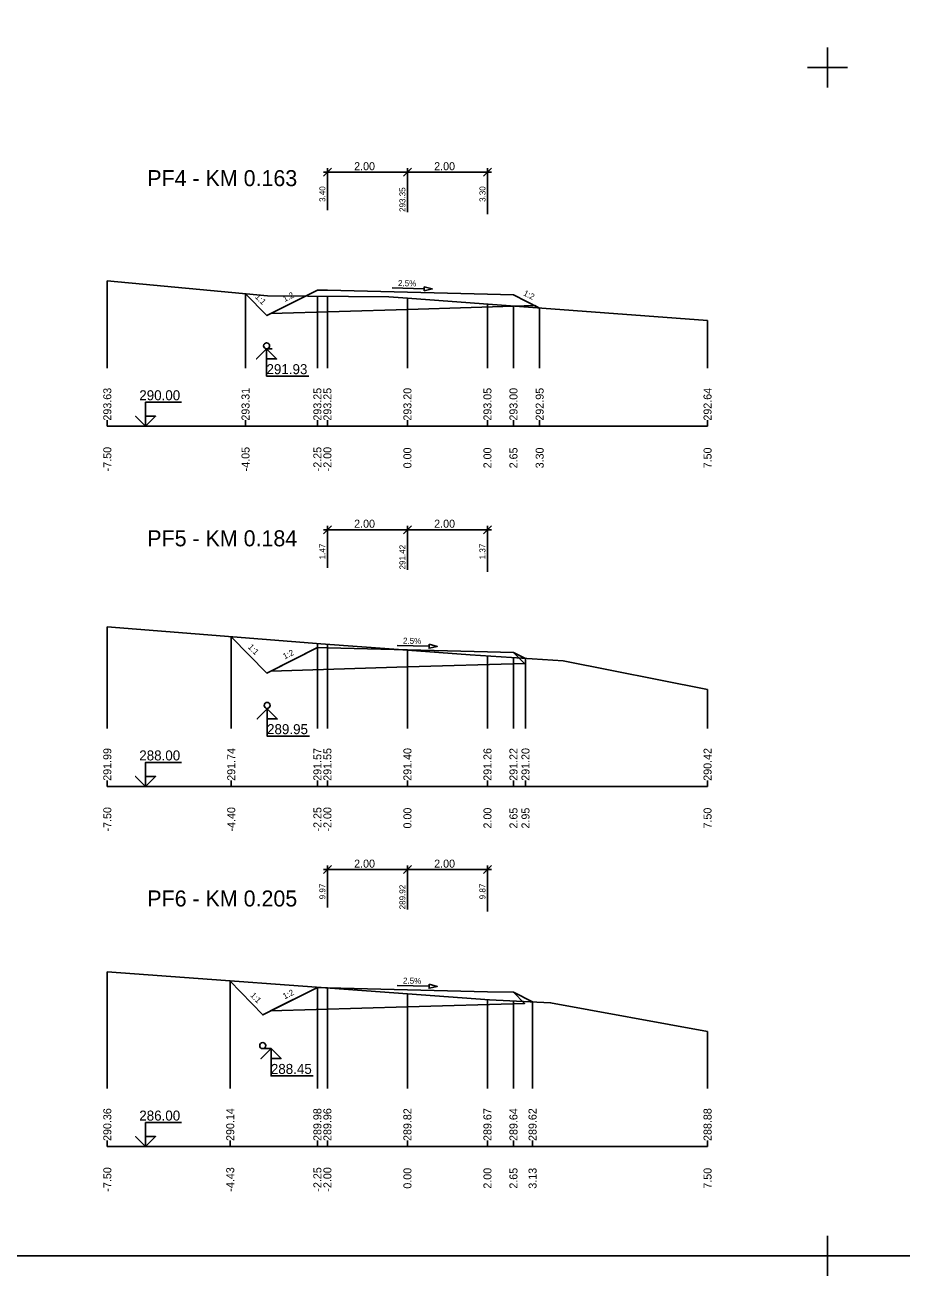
# Model space of a CAD drawing. Extents: x -5 to 1895, y -2 to 602.
# Drawn here: x 219.4 to 438.6, y -2.3 to 310.3 of the extents above; entities that cross this region are included whole.
import ezdxf

# ---------------------------------------------------------------- set-up
doc = ezdxf.new("R2010")
doc.units = 0
for name, color, linetype in [('KOTA', 7, 'Continuous'), ('KOTA_DELKY', 7, 'Continuous'), ('KOTA_DELKY_CONT', 7, 'Continuous'), ('KRIZENI', 7, 'Continuous'), ('NS_TELESO_VOZOVKY', 7, 'Continuous'), ('NS_V_PF', 7, 'Continuous'), ('REZY_PF_PUVODNI', 7, 'Continuous'), ('SESTAVY_REZU_PF', 7, 'Continuous'), ('SKLON', 7, 'Continuous'), ('SVK', 7, 'Continuous')]:
    doc.layers.add(name, color=color, linetype=linetype)

msp = doc.modelspace()

# ---------------------------------------------------------------- linework, layer by layer
for p, q in [((420, 304.67), (420, 294.67)), ((420, 304.67), (420, 294.67)), ((420, 304.67), (420, 294.67)), ((420, 304.67), (420, 294.67)), ((420, 304.67), (420, 294.67)), ((420, 304.67), (420, 294.67)), ((420, 304.67), (420, 294.67)), ((420, 304.67), (420, 294.67)), ((420, 304.67), (420, 294.67)), ((420, 304.67), (420, 294.67)), ((420, 304.67), (420, 294.67)), ((420, 304.67), (420, 294.67)), ((420, 304.67), (420, 294.67)), ((420, 304.67), (420, 294.67)), ((420, 304.67), (420, 294.67)), ((420, 304.67), (420, 294.67)), ((420, 304.67), (420, 294.67)), ((420, 304.67), (420, 294.67)), ((420, 304.67), (420, 294.67)), ((420, 304.67), (420, 294.67)), ((420, 304.67), (420, 294.67)), ((420, 304.67), (420, 294.67)), ((420, 304.67), (420, 294.67)), ((420, 304.67), (420, 294.67)), ((420, 304.67), (420, 294.67)), ((420, 304.67), (420, 294.67)), ((420, 304.67), (420, 294.67)), ((420, 304.67), (420, 294.67)), ((420, 304.67), (420, 294.67)), ((420, 304.67), (420, 294.67)), ((420, 304.67), (420, 294.67)), ((420, 304.67), (420, 294.67)), ((420, 304.67), (420, 294.67)), ((420, 304.67), (420, 294.67)), ((420, 304.67), (420, 294.67)), ((420, 304.67), (420, 294.67)), ((420, 304.67), (420, 294.67)), ((420, 304.67), (420, 294.67)), ((420, 304.67), (420, 294.67)), ((420, 304.67), (420, 294.67)), ((420, 304.67), (420, 294.67)), ((420, 304.67), (420, 294.67)), ((420, 304.67), (420, 294.67)), ((420, 304.67), (420, 294.67)), ((420, 304.67), (420, 294.67)), ((420, 304.67), (420, 294.67)), ((420, 304.67), (420, 294.67)), ((420, 304.67), (420, 294.67)), ((420, 304.67), (420, 294.67)), ((420, 304.67), (420, 294.67)), ((420, 304.67), (420, 294.67)), ((420, 304.67), (420, 294.67)), ((420, 304.67), (420, 294.67)), ((420, 304.67), (420, 294.67)), ((425, 299.67), (415, 299.67)), ((425, 299.67), (415, 299.67)), ((425, 299.67), (415, 299.67)), ((425, 299.67), (415, 299.67)), ((425, 299.67), (415, 299.67)), ((425, 299.67), (415, 299.67)), ((425, 299.67), (415, 299.67)), ((425, 299.67), (415, 299.67)), ((425, 299.67), (415, 299.67)), ((425, 299.67), (415, 299.67)), ((425, 299.67), (415, 299.67)), ((425, 299.67), (415, 299.67)), ((425, 299.67), (415, 299.67)), ((425, 299.67), (415, 299.67)), ((425, 299.67), (415, 299.67)), ((425, 299.67), (415, 299.67)), ((425, 299.67), (415, 299.67)), ((425, 299.67), (415, 299.67)), ((425, 299.67), (415, 299.67)), ((425, 299.67), (415, 299.67)), ((425, 299.67), (415, 299.67)), ((425, 299.67), (415, 299.67)), ((425, 299.67), (415, 299.67)), ((425, 299.67), (415, 299.67)), ((425, 299.67), (415, 299.67)), ((425, 299.67), (415, 299.67)), ((425, 299.67), (415, 299.67)), ((425, 299.67), (415, 299.67)), ((425, 299.67), (415, 299.67)), ((425, 299.67), (415, 299.67)), ((425, 299.67), (415, 299.67)), ((425, 299.67), (415, 299.67)), ((425, 299.67), (415, 299.67)), ((425, 299.67), (415, 299.67)), ((425, 299.67), (415, 299.67)), ((425, 299.67), (415, 299.67)), ((425, 299.67), (415, 299.67)), ((425, 299.67), (415, 299.67)), ((425, 299.67), (415, 299.67)), ((425, 299.67), (415, 299.67)), ((425, 299.67), (415, 299.67)), ((425, 299.67), (415, 299.67)), ((425, 299.67), (415, 299.67)), ((425, 299.67), (415, 299.67)), ((425, 299.67), (415, 299.67)), ((425, 299.67), (415, 299.67)), ((425, 299.67), (415, 299.67)), ((425, 299.67), (415, 299.67)), ((425, 299.67), (415, 299.67)), ((425, 299.67), (415, 299.67)), ((425, 299.67), (415, 299.67)), ((425, 299.67), (415, 299.67)), ((425, 299.67), (415, 299.67)), ((425, 299.67), (415, 299.67)), ((420, 7.67), (420, -2.33)), ((420, 7.67), (420, -2.33)), ((420, 7.67), (420, -2.33)), ((420, 7.67), (420, -2.33)), ((420, 7.67), (420, -2.33)), ((420, 7.67), (420, -2.33)), ((420, 7.67), (420, -2.33)), ((420, 7.67), (420, -2.33)), ((420, 7.67), (420, -2.33)), ((420, 7.67), (420, -2.33)), ((420, 7.67), (420, -2.33)), ((420, 7.67), (420, -2.33)), ((425, 2.67), (415, 2.67)), ((425, 2.67), (415, 2.67)), ((425, 2.67), (415, 2.67)), ((425, 2.67), (415, 2.67)), ((425, 2.67), (415, 2.67)), ((425, 2.67), (415, 2.67)), ((425, 2.67), (415, 2.67)), ((425, 2.67), (415, 2.67)), ((425, 2.67), (415, 2.67)), ((425, 2.67), (415, 2.67)), ((425, 2.67), (415, 2.67)), ((425, 2.67), (415, 2.67))]:
    msp.add_line(p, q)
msp.add_lwpolyline([(0, 596.67), (1890, 596.67), (1890, 2.67), (0, 2.67)], close=True)
at = {"layer": 'KOTA'}
for points in [[(279.82, 229.35), (277.32, 226.85), (279.82, 229.35), (279.82, 222.52), (290.37, 222.52)], [(279.82, 229.35), (281.19, 229.35)], [(279.82, 229.35), (282.32, 226.85), (279.82, 226.85), (279.82, 229.35)], [(279.82, 229.35), (282.32, 226.85), (279.82, 226.85)], [(249.57, 210), (247.07, 212.5), (249.57, 210), (249.57, 216), (258.57, 216)], [(249.57, 210), (252.07, 212.5), (249.57, 212.5), (249.57, 210)], [(249.57, 210), (252.07, 212.5), (249.57, 212.5)], [(279.97, 139.38), (277.47, 136.88), (279.97, 139.38), (279.97, 132.56), (290.51, 132.56)], [(279.97, 139.38), (282.47, 136.88), (279.97, 136.88), (279.97, 139.38)], [(279.97, 139.38), (282.47, 136.88), (279.97, 136.88)], [(249.57, 120), (247.07, 122.5), (249.57, 120), (249.57, 126), (258.57, 126)], [(249.57, 120), (252.07, 122.5), (249.57, 122.5), (249.57, 120)], [(249.57, 120), (252.07, 122.5), (249.57, 122.5)], [(280.92, 54.48), (278.42, 51.98), (280.92, 54.48), (280.92, 47.66), (291.46, 47.66)], [(278.83, 54.48), (280.92, 54.48)], [(280.92, 54.48), (283.42, 51.98), (280.92, 51.98), (280.92, 54.48)], [(280.92, 54.48), (283.42, 51.98), (280.92, 51.98)], [(249.57, 30), (247.07, 32.5), (249.57, 30), (249.57, 36), (258.57, 36)], [(249.57, 30), (252.07, 32.5), (249.57, 32.5), (249.57, 30)], [(249.57, 30), (252.07, 32.5), (249.57, 32.5)]]:
    msp.add_lwpolyline(points, dxfattribs=at)
at = {"layer": 'KOTA_DELKY'}
for points in [[(294, 272.48), (296, 274.48)], [(294, 273.48), (316, 273.48)], [(295, 263.98), (295, 274.48)], [(314, 272.48), (316, 274.48)], [(314, 272.48), (316, 274.48)], [(314, 273.48), (336, 273.48)], [(315, 263.48), (315, 274.48)], [(315, 263.48), (315, 274.48)], [(334, 272.48), (336, 274.48)], [(335, 262.98), (335, 274.48)], [(294, 183.15), (296, 185.15)], [(295, 174.65), (295, 185.15)], [(314, 183.15), (316, 185.15)], [(314, 183.15), (316, 185.15)], [(315, 174.15), (315, 185.15)], [(315, 174.15), (315, 185.15)], [(334, 183.15), (336, 185.15)], [(335, 173.65), (335, 185.15)], [(294, 184.15), (316, 184.15)], [(314, 184.15), (336, 184.15)], [(294, 98.21), (296, 100.21)], [(295, 89.71), (295, 100.21)], [(314, 98.21), (316, 100.21)], [(314, 98.21), (316, 100.21)], [(315, 89.21), (315, 100.21)], [(315, 89.21), (315, 100.21)], [(334, 98.21), (336, 100.21)], [(335, 88.71), (335, 100.21)], [(294, 99.21), (316, 99.21)], [(314, 99.21), (336, 99.21)]]:
    msp.add_lwpolyline(points, dxfattribs=at)
at = {"layer": 'KRIZENI'}
for centre in [(279.82, 230.1), (279.94, 140.25), (278.83, 55.23)]:
    msp.add_circle(centre, 0.75, dxfattribs=at)
at = {"layer": 'NS_TELESO_VOZOVKY'}
for points in [[(315, 243.48), (335, 242.98), (341.5, 242.82), (348.04, 239.55), (346.86, 240.14), (315, 239.18), (280.83, 238.16), (292.5, 244.04), (295, 243.98), (315, 243.48)], [(315, 154.15), (335, 153.65), (341.5, 153.49), (344.26, 150.73), (315, 149.85), (280.83, 148.83), (292.5, 154.71), (295, 154.65), (315, 154.15)], [(315, 69.21), (335, 68.71), (341.5, 68.55), (344.26, 65.79), (315, 64.91), (280.82, 63.89), (292.5, 69.77), (295, 69.71), (315, 69.21)]]:
    msp.add_lwpolyline(points, dxfattribs=at)
at = {"layer": 'NS_V_PF'}
for points in [[(274.54, 243.11), (279.87, 237.67), (292.5, 244.04), (295, 243.98), (315, 243.48), (335, 242.98), (341.5, 242.82), (348.04, 239.55)], [(270.97, 157.42), (279.87, 148.34), (292.5, 154.71), (295, 154.65), (315, 154.15), (335, 153.65), (341.5, 153.49), (344.5, 151.99)], [(270.64, 71.42), (278.85, 62.9), (292.5, 69.77), (295, 69.71), (315, 69.21), (335, 68.71), (341.5, 68.55), (346.27, 66.16)]]:
    msp.add_lwpolyline(points, dxfattribs=at)
at = {"layer": 'REZY_PF_PUVODNI'}
for points in [[(240, 246.34), (280.06, 242.59), (310.35, 242.37), (315, 242.02), (390, 236.41)], [(240, 159.87), (293.33, 155.65), (315, 154.05), (315, 154.05), (330.64, 152.89), (353.95, 151.37), (390, 144.21)], [(240, 73.65), (315, 68.19), (335.5, 66.7), (350.76, 65.94), (390, 58.77)]]:
    msp.add_lwpolyline(points, dxfattribs=at)
at = {"layer": 'SESTAVY_REZU_PF'}
for points in [[(240, 210), (390, 210)], [(240, 120), (390, 120)], [(240, 30), (390, 30)]]:
    msp.add_lwpolyline(points, dxfattribs=at)
at = {"layer": 'SKLON'}
for points in [[(311.21, 244.58), (319.21, 244.38)], [(319.22, 244.88), (321.21, 244.33), (319.2, 243.88), (319.22, 244.88)], [(312.45, 155.22), (320.45, 155.02)], [(320.46, 155.52), (322.45, 154.97), (320.43, 154.52), (320.46, 155.52)], [(312.45, 70.28), (320.45, 70.08)], [(320.46, 70.58), (322.45, 70.03), (320.43, 69.58), (320.46, 70.58)]]:
    msp.add_lwpolyline(points, dxfattribs=at)
for points in [[(319.22, 244.88), (321.21, 244.33), (319.2, 243.88)], [(320.46, 155.52), (322.45, 154.97), (320.43, 154.52)], [(320.46, 70.58), (322.45, 70.03), (320.43, 69.58)]]:
    msp.add_lwpolyline(points, close=True, dxfattribs=at)
at = {"layer": 'SVK'}
for points in [[(240, 224.5), (240, 246.34)], [(274.54, 224.5), (274.54, 243.11)], [(292.5, 224.5), (292.5, 242.5)], [(295, 224.5), (295, 242.48)], [(315, 224.5), (315, 242.02)], [(335, 224.5), (335, 240.52)], [(341.5, 224.5), (341.5, 240.04)], [(348.04, 224.5), (348.04, 239.55)], [(390, 224.5), (390, 236.41)], [(240, 210), (240, 211.5)], [(274.54, 210), (274.54, 211.5)], [(292.5, 210), (292.5, 211.5)], [(295, 210), (295, 211.5)], [(315, 210), (315, 211.5)], [(335, 210), (335, 211.5)], [(341.5, 210), (341.5, 211.5)], [(348.04, 210), (348.04, 211.5)], [(390, 210), (390, 211.5)], [(240, 134.5), (240, 159.87)], [(270.97, 134.5), (270.97, 157.42)], [(292.5, 134.5), (292.5, 155.72)], [(295, 134.5), (295, 155.53)], [(315, 134.5), (315, 154.05)], [(335, 134.5), (335, 152.61)], [(341.5, 134.5), (341.5, 152.18)], [(344.5, 134.5), (344.5, 151.99)], [(390, 134.5), (390, 144.21)], [(240, 120), (240, 121.5)], [(270.97, 120), (270.97, 121.5)], [(292.5, 120), (292.5, 121.5)], [(295, 120), (295, 121.5)], [(315, 120), (315, 121.5)], [(335, 120), (335, 121.5)], [(341.5, 120), (341.5, 121.5)], [(344.5, 120), (344.5, 121.5)], [(390, 120), (390, 121.5)], [(240, 44.5), (240, 73.65)], [(270.72, 44.5), (270.72, 71.41)], [(292.5, 44.5), (292.5, 69.83)], [(295, 44.5), (295, 69.64)], [(315, 44.5), (315, 68.19)], [(335, 44.5), (335, 66.73)], [(341.5, 44.5), (341.5, 66.4)], [(346.27, 44.5), (346.27, 66.16)], [(390, 44.5), (390, 58.77)], [(240, 30), (240, 31.5)], [(270.72, 30), (270.72, 31.5)], [(292.5, 30), (292.5, 31.5)], [(295, 30), (295, 31.5)], [(315, 30), (315, 31.5)], [(335, 30), (335, 31.5)], [(341.5, 30), (341.5, 31.5)], [(346.27, 30), (346.27, 31.5)], [(390, 30), (390, 31.5)]]:
    msp.add_lwpolyline(points, dxfattribs=at)

# ---------------------------------------------------------------- texts
at = {"layer": 'KOTA'}
for s, p in [('291.93', (279.78, 223.02)), ('290.00', (247.99, 216.5)), ('289.95', (279.92, 133.06)), ('288.00', (247.99, 126.5)), ('288.45', (280.87, 48.16)), ('286.00', (247.99, 36.5))]:
    msp.add_text(s, height=2.5, dxfattribs=at).set_placement(p)
at = {"layer": 'KOTA_DELKY'}
for p in [(301.69, 273.98), (321.69, 273.98), (301.69, 184.65), (321.69, 184.65), (301.69, 99.71), (321.69, 99.71)]:
    msp.add_text('2.00', height=2, dxfattribs=at).set_placement(p)
at = {"layer": 'KOTA_DELKY_CONT'}
for s, p in [('3.40', (294.5, 266.07)), ('293.35', (314.5, 263.56)), ('3.30', (334.5, 266.07)), ('1.47', (294.5, 176.74)), ('291.42', (314.5, 174.23)), ('1.37', (334.5, 176.74)), ('9.97', (294.5, 91.8)), ('289.92', (314.5, 89.29)), ('9.87', (334.5, 91.8))]:
    msp.add_text(s, height=1.5, rotation=90, dxfattribs=at).set_placement(p)
at = {"layer": 'SESTAVY_REZU_PF'}
for s, p in [('PF4 - KM 0.163', (250, 270)), ('PF5 - KM 0.184', (250, 180)), ('PF6 - KM 0.205', (250, 90))]:
    msp.add_text(s, height=4, dxfattribs=at).set_placement(p)
at = {"layer": 'SKLON'}
for s, rotation, p in [('2.5%', 358.5679, (312.63, 245.04)), ('1:2', 333.4349, (343.81, 242.78)), ('1:1', 314.4213, (276.81, 242.21)), ('1:2', 26.7649, (284.32, 241.04)), ('2.5%', 358.5679, (313.87, 155.68)), ('1:1', 314.4213, (275.03, 154.71)), ('1:2', 26.7649, (284.32, 151.71)), ('2.5%', 358.5679, (313.87, 70.74)), ('1:2', 26.7501, (284.32, 66.77)), ('1:1', 313.9573, (275.62, 67.7))]:
    msp.add_text(s, height=1.5, rotation=rotation, dxfattribs=at).set_placement(p)
at = {"layer": 'SVK'}
for s, p in [(' 293.63', (241, 210.67)), (' 293.31', (275.54, 210.67)), (' 293.25', (293.5, 210.67)), (' 293.25', (296, 210.67)), (' 293.20', (316, 210.67)), (' 293.05', (336, 210.67)), (' 293.00', (342.5, 210.67)), (' 292.95', (349.04, 210.67)), (' 292.64', (391, 210.67)), (' -7.50', (241, 198)), (' -4.05', (275.54, 198)), (' -2.25', (293.5, 198)), (' -2.00', (296, 198)), ('  0.00', (316, 198)), ('  2.00', (336, 198)), ('  2.65', (342.5, 198)), ('  3.30', (349.04, 198)), ('  7.50', (391, 198)), (' 291.99', (241, 120.67)), (' 291.74', (271.97, 120.67)), (' 291.57', (293.5, 120.67)), (' 291.55', (296, 120.67)), (' 291.40', (316, 120.67)), (' 291.26', (336, 120.67)), (' 291.22', (342.5, 120.67)), (' 291.20', (345.5, 120.67)), (' 290.42', (391, 120.67)), (' -7.50', (241, 108)), (' -4.40', (271.97, 108)), (' -2.25', (293.5, 108)), (' -2.00', (296, 108)), ('  0.00', (316, 108)), ('  2.00', (336, 108)), ('  2.65', (342.5, 108)), ('  2.95', (345.5, 108)), ('  7.50', (391, 108)), (' 290.36', (241, 30.67)), (' 290.14', (271.72, 30.67)), (' 289.98', (293.5, 30.67)), (' 289.96', (296, 30.67)), (' 289.82', (316, 30.67)), (' 289.67', (336, 30.67)), (' 289.64', (342.5, 30.67)), (' 289.62', (347.27, 30.67)), (' 288.88', (391, 30.67)), (' -7.50', (241, 18)), (' -4.43', (271.72, 18)), (' -2.25', (293.5, 18)), (' -2.00', (296, 18)), ('  0.00', (316, 18)), ('  2.00', (336, 18)), ('  2.65', (342.5, 18)), ('  3.13', (347.27, 18)), ('  7.50', (391, 18))]:
    msp.add_text(s, height=2, rotation=90, dxfattribs=at).set_placement(p)

doc.saveas('drawing.dxf')
